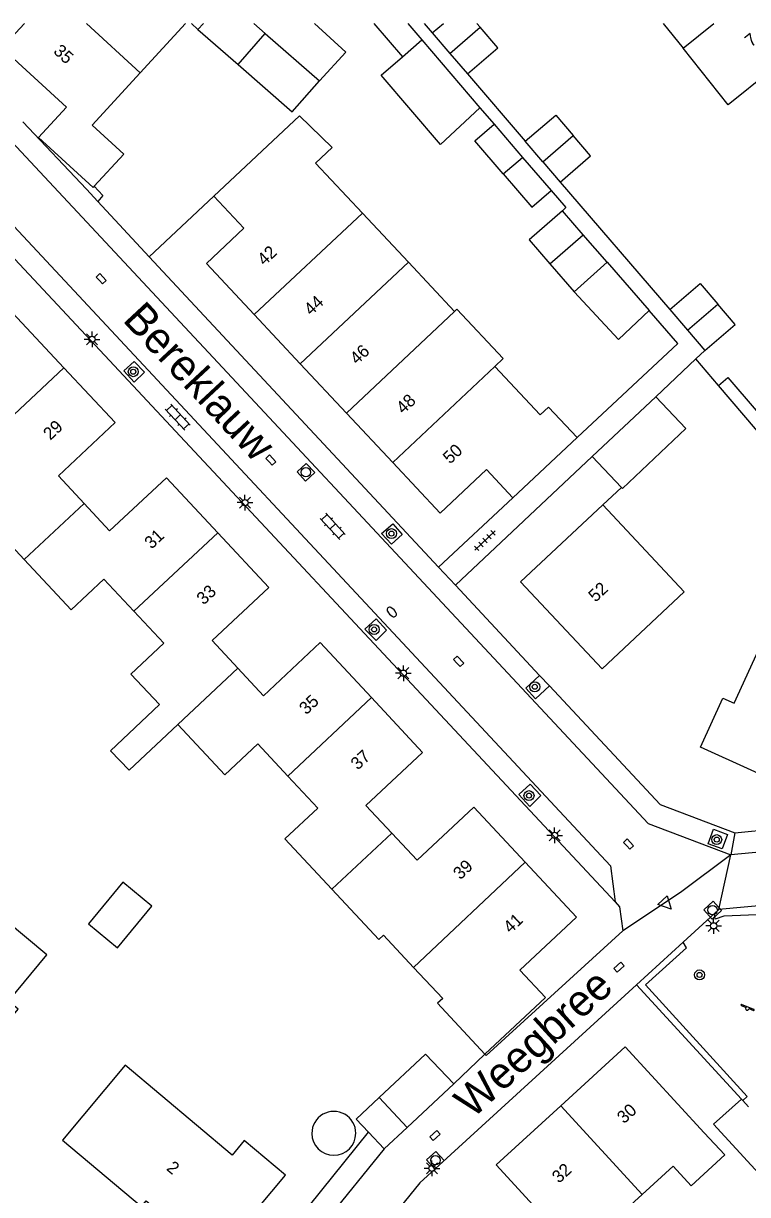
# Model space of a CAD drawing. Extents: x 136000 to 141000, y 400494 to 402006.
# Drawn here: x 137335.3 to 137393.1, y 401906.5 to 402000 of the extents above; entities that cross this region are included whole.
import ezdxf

# ---------------------------------------------------------------- set-up
doc = ezdxf.new("R2010")
doc.units = 0
for name, color, linetype in [('gg-afsc-erfafscheiding', 7, 'Continuous'), ('gg-afsc-muur', 7, 'Continuous'), ('gg-anno-huisnummerreeks BGT', 7, 'Continuous'), ('gg-anno-openbare ruimte label', 7, 'Continuous'), ('gg-bbg-bijgebouw', 7, 'Continuous'), ('gg-bbg-gedigitaliseerde bebouwing', 7, 'Continuous'), ('gg-bbg-gedigitaliseerde bijgebouw', 7, 'Continuous'), ('gg-bbg-hoofdgebouw', 7, 'Continuous'), ('gg-bbg-luifel en loopbrug', 7, 'Continuous'), ('gg-bbg-tussenscheiding', 7, 'Continuous'), ('gg-knt-verharding', 7, 'Continuous'), ('gg-knt-verharding nz', 7, 'Continuous'), ('gt-grn-groengrens', 7, 'Continuous'), ('gt-grn-weggrens', 7, 'Continuous'), ('gt-symb-boom', 7, 'Continuous'), ('gt-symb-brandkraan', 7, 'Continuous'), ('gt-symb-klinker verharding', 7, 'Continuous'), ('gt-symb-kolk', 7, 'Continuous'), ('gt-symb-lichtmast', 7, 'Continuous'), ('gt-symb-rioolschacht', 7, 'Continuous'), ('gt-symb-speelvoorziening', 7, 'Continuous'), ('gt-symb-tegel verharding', 7, 'Continuous'), ('gt-symb-waterafsluiter', 7, 'Continuous')]:
    doc.layers.add(name, color=color, linetype=linetype)

# ---------------------------------------------------------------- blocks, each defined once
blk = doc.blocks.new('gt0-SV')
at = {"layer": 'gt-symb-speelvoorziening'}
for p, q in [((-0.477, 0.255), (-0.08, 0.096)), ((0.542, -0.076), (-0.449, 0.324)), ((0.125, 0.014), (0.515, -0.143))]:
    blk.add_line(p, q, dxfattribs=at)
for centre, radius, start, end in [((-0.466, 0.291), 0.0369, 63.6251, 252.66016), ((-0.002, -0.005), 0.128, 127.68665, 8.59861), ((0.531, -0.111), 0.0363, 243.50852, 72.54358)]:
    blk.add_arc(centre, radius, start, end, dxfattribs=at)
blk = doc.blocks.new('gt0-WAFSL')
at = {"layer": 'gt-symb-waterafsluiter'}
for p, q in [((-0.5, -0.333), (0, 0.667)), ((0, 0.667), (0.5, -0.333)), ((0.5, -0.333), (-0.5, -0.333))]:
    blk.add_line(p, q, dxfattribs=at)
blk = doc.blocks.new('gt0-BOOM')
at = {"layer": 'gt-symb-boom'}
for radius in [0.4, 0.2]:
    blk.add_circle((0, 0), radius, dxfattribs=at)
blk = doc.blocks.new('gt0-RS')
at = {"layer": 'gt-symb-rioolschacht'}
blk.add_lwpolyline([(-0.5, -0.5), (0.5, -0.5), (0.5, 0.5), (-0.5, 0.5)], close=True, dxfattribs=at)
blk.add_circle((0, 0), 0.375, dxfattribs=at)
blk = doc.blocks.new('gt0-LMAST')
at = {"layer": 'gt-symb-lichtmast'}
for p, q in [((-0.182, 0.173), (-0.447, 0.438)), ((-0.005, 0.246), (-0.005, 0.621)), ((0.172, 0.173), (0.437, 0.438)), ((-0.255, -0.004), (-0.63, -0.004)), ((-0.182, -0.181), (-0.447, -0.446)), ((-0.005, -0.254), (-0.005, -0.629)), ((0.437, -0.446), (0.172, -0.181)), ((0.245, -0.004), (0.62, -0.004))]:
    blk.add_line(p, q, dxfattribs=at)
blk.add_circle((-0.005, -0.004), 0.25, dxfattribs=at)
blk = doc.blocks.new('gt0-KOLK')
at = {"layer": 'gt-symb-kolk'}
blk.add_lwpolyline([(0, 0), (0.375, 0), (0.375, 0.4), (-0.375, 0.4), (-0.375, 0), (0, 0)], dxfattribs=at)
blk = doc.blocks.new('gt0-BR')
at = {"layer": 'gt-symb-brandkraan'}
for centre, radius, start, end in [((-0.244, 0), 0.206, 107.56694, 252.43307), ((0.599, -2.664), 3, 106.89205, 107.56694), ((0, -0.691), 0.938, 73.10799, 106.89205), ((-0.599, -2.664), 3, 72.43309, 73.10799), ((0.244, 0), 0.206, 287.56695, 72.43309), ((0.599, 2.664), 3, 252.43307, 253.10797), ((0, 0.691), 0.938, 253.10797, 286.89206), ((-0.599, 2.664), 3, 286.89206, 287.56695)]:
    blk.add_arc(centre, radius, start, end, dxfattribs=at)
blk = doc.blocks.new('gt0-TEG1')
at = {"layer": 'gt-symb-tegel verharding'}
for p, q in [((-1.125, 0), (1.125, 0)), ((-0.9, -0.25), (-0.9, 0.25)), ((-0.45, -0.25), (-0.45, 0.25)), ((0, -0.25), (0, 0.25)), ((0.45, -0.25), (0.45, 0.25)), ((0.9, -0.25), (0.9, 0.25))]:
    blk.add_line(p, q, dxfattribs=at)
blk = doc.blocks.new('gt0-KL1')
at = {"layer": 'gt-symb-klinker verharding'}
for p, q in [((-1.15, 0.3), (1.15, 0.3)), ((-1, -0.3), (-1, 0.3)), ((-0.5, 0.3), (-0.5, 0.45)), ((0, -0.3), (0, 0.3)), ((0.5, 0.3), (0.5, 0.45)), ((1, -0.3), (1, 0.3)), ((-1.15, -0.3), (1.15, -0.3)), ((-0.5, -0.45), (-0.5, -0.3)), ((0.5, -0.45), (0.5, -0.3))]:
    blk.add_line(p, q, dxfattribs=at)

msp = doc.modelspace()

# ---------------------------------------------------------------- linework, layer by layer
at = {"layer": 'gg-afsc-erfafscheiding'}
for p, q in [((137367.313, 402000), (137367.96, 401999.24)), ((137370.76, 401995.98), (137375.39, 401990.59)), ((137371.768, 401993.268), (137372.9, 401991.95)), ((137378.18, 401987.33), (137386.938, 401977.157)), ((137387.571, 401974.458), (137385.29, 401977.079)), ((137387.571, 401974.458), (137379.526, 401966.944)), ((137389.017, 401973.217), (137389.732, 401973.893)), ((137385.826, 401970.196), (137389.017, 401973.217)), ((137390.824, 401971.097), (137389.017, 401973.217))]:
    msp.add_line(p, q, dxfattribs=at)
for points in [[(137340.95, 401986.998), (137341.653, 401986.269), (137341.254, 401985.787)], [(137377.45, 401986.66), (137378.64, 401985.293), (137378.357, 401985.047)], [(137390.824, 401971.097), (137391.577, 401971.738), (137393.83, 401969.11)], [(137401.97, 401961.65), (137396.88, 401963.99), (137390.824, 401971.097)]]:
    msp.add_lwpolyline(points, dxfattribs=at)
at = {"layer": 'gg-afsc-muur'}
for p, q in [((137345.355, 401981.368), (137350.52, 401986.21)), ((137341.254, 401985.787), (137345.355, 401981.368)), ((137381.581, 401961.565), (137383.065, 401962.953)), ((137369.67, 401915.333), (137372.17, 401917.72))]:
    msp.add_line(p, q, dxfattribs=at)
at = {"layer": 'gg-bbg-bijgebouw'}
for p, q in [((137349.247, 401999.516), (137349.691, 402000)), ((137386.938, 401977.157), (137388.34, 401975.519)), ((137388.34, 401975.519), (137389.732, 401973.893)), ((137385.826, 401970.196), (137380.734, 401965.416)), ((137380.734, 401965.416), (137383.065, 401962.953)), ((137383.065, 401962.953), (137383.142, 401962.872)), ((137390.433, 401912.12), (137392.65, 401914.12)), ((137392.65, 401914.12), (137392.752, 401914.008)), ((137392.752, 401914.008), (137393.218, 401913.498)), ((137361.873, 401912.525), (137362.862, 401911.475)), ((137362.862, 401911.475), (137364.115, 401910.146)), ((137364.115, 401910.146), (137365.942, 401911.852))]:
    msp.add_line(p, q, dxfattribs=at)
at = {"layer": 'gg-bbg-gedigitaliseerde bebouwing'}
for p, q in [((137344.632, 401996.057), (137348.258, 402000)), ((137386.412, 402000), (137387.986, 401998.031)), ((137354.619, 401999.204), (137358.94, 401995.41)), ((137344.632, 401996.057), (137340.789, 401991.878)), ((137350.52, 401986.21), (137357.353, 401992.613)), ((137358.645, 401988.848), (137362.381, 401984.863)), ((137340.95, 401986.998), (137340.869, 401986.911)), ((137362.381, 401984.863), (137366.058, 401980.941)), ((137366.058, 401980.941), (137369.745, 401977.008)), ((137377.243, 401969.372), (137379.526, 401966.944)), ((137364.065, 401927.218), (137366.472, 401924.641))]:
    msp.add_line(p, q, dxfattribs=at)
for points in [[(137358.94, 401995.41), (137361.043, 401997.703), (137358.545, 402000)], [(137398.35, 401998.92), (137391.6, 401993.51), (137387.986, 401998.031)], [(137357.353, 401992.613), (137359.97, 401990.09), (137358.645, 401988.848)], [(137340.789, 401991.878), (137343.313, 401989.558), (137340.95, 401986.998)], [(137369.745, 401977.008), (137369.934, 401977.186), (137373.634, 401973.24), (137372.952, 401972.601)], [(137372.952, 401972.601), (137376.57, 401968.741), (137377.243, 401969.372)], [(137331.85, 401966.23), (137334.24, 401963.67), (137331.61, 401961.21), (137335.358, 401957.198)], [(137381.581, 401961.565), (137388.09, 401954.62), (137381.53, 401948.47)], [(137335.358, 401957.198), (137339.11, 401953.18), (137341.74, 401955.63), (137344.132, 401953.072)], [(137344.132, 401953.072), (137346.52, 401950.52), (137343.89, 401948.06)], [(137391.164, 401946.137), (137392.07, 401945.73), (137395.31, 401952.82), (137402.47, 401949.55)], [(137343.89, 401948.06), (137346.185, 401945.621), (137342.271, 401941.938), (137343.743, 401940.374), (137347.64, 401944.04)], [(137347.64, 401944.04), (137351.39, 401940.02), (137354.02, 401942.48), (137356.42, 401939.91)], [(137356.42, 401939.91), (137358.81, 401937.35), (137356.18, 401934.9), (137359.93, 401930.88)], [(137331.835, 401917.611), (137334.892, 401921.305), (137334.118, 401921.945), (137337.18, 401925.651), (137330.802, 401930.927), (137331.861, 401932.209), (137326.714, 401936.459)], [(137359.93, 401930.88), (137363.68, 401926.86), (137364.065, 401927.218)], [(137366.472, 401924.641), (137368.801, 401922.148), (137368.382, 401921.776), (137372.17, 401917.72)], [(137356.249, 401908.039), (137352.939, 401910.813), (137351.972, 401909.66), (137343.433, 401916.824), (137338.416, 401910.857)], [(137389.68, 401911.44), (137391.316, 401909.667), (137388.64, 401907.21), (137387.2, 401908.78), (137384.728, 401906.513)], [(137384.728, 401906.513), (137382.26, 401904.25), (137383.69, 401902.68), (137381, 401900.22), (137373.07, 401908.87)]]:
    msp.add_lwpolyline(points, dxfattribs=at)
at = {"layer": 'gg-bbg-gedigitaliseerde bijgebouw'}
for p, q in [((137363.297, 402000), (137365.58, 401997.34)), ((137365.996, 402000), (137367.12, 401998.68)), ((137367.96, 401999.24), (137368.852, 402000)), ((137371.53, 402000), (137371.79, 401999.697)), ((137349.247, 401999.516), (137352.444, 401996.718)), ((137352.444, 401996.718), (137354.619, 401999.204)), ((137367.96, 401999.24), (137369.36, 401997.61)), ((137365.58, 401997.34), (137367.12, 401998.68)), ((137369.36, 401997.61), (137370.76, 401995.98)), ((137372.9, 401991.95), (137375.175, 401989.305)), ((137376.785, 401988.96), (137375.39, 401990.59)), ((137375.175, 401989.305), (137377.45, 401986.66)), ((137376.785, 401988.96), (137378.18, 401987.33)), ((137377.338, 401980.813), (137380.022, 401983.133)), ((137381.919, 401980.953), (137380.022, 401983.133)), ((137377.338, 401980.813), (137379.28, 401978.566)), ((137381.919, 401980.953), (137385.29, 401977.079)), ((137363.711, 401914.241), (137361.873, 401912.525)), ((137365.942, 401911.852), (137363.711, 401914.241)), ((137396.53, 401905.46), (137390.433, 401912.12))]:
    msp.add_line(p, q, dxfattribs=at)
for points in [[(137370.76, 401995.98), (137373.19, 401998.06), (137371.79, 401999.697)], [(137375.39, 401990.59), (137377.82, 401992.67), (137379.218, 401991.042)], [(137373.632, 401987.982), (137371.36, 401990.63), (137372.9, 401991.95)], [(137378.18, 401987.33), (137380.61, 401989.42), (137379.218, 401991.042)], [(137373.632, 401987.982), (137375.9, 401985.34), (137377.45, 401986.66)], [(137379.28, 401978.566), (137382.842, 401974.778), (137385.29, 401977.079)], [(137386.938, 401977.157), (137389.35, 401979.23), (137390.755, 401977.594)], [(137389.732, 401973.893), (137392.15, 401975.97), (137390.755, 401977.594)], [(137383.142, 401962.872), (137388.22, 401967.65), (137385.826, 401970.196)]]:
    msp.add_lwpolyline(points, dxfattribs=at)
for start, end in [(0.01636, 180.04903), (180.04905, 0.01634)]:
    msp.add_arc((137360.096, 401911.392), 1.753, start, end, dxfattribs=at)
at = {"layer": 'gg-bbg-hoofdgebouw'}
for p, q in [((137333.58, 401998.04), (137335.378, 402000)), ((137357.417, 401972.833), (137353.728, 401976.773)), ((137361.114, 401968.884), (137357.417, 401972.833)), ((137364.803, 401964.944), (137361.114, 401968.884)), ((137379.526, 401966.944), (137374.393, 401962.136)), ((137381.581, 401961.565), (137375.01, 401955.42)), ((137375.01, 401955.42), (137381.53, 401948.47)), ((137373.07, 401908.87), (137378.235, 401913.598))]:
    msp.add_line(p, q, dxfattribs=at)
for points in [[(137333.58, 401998.04), (137338.747, 401993.319), (137336.521, 401990.883), (137340.869, 401986.911)], [(137353.728, 401976.773), (137349.92, 401980.84), (137352.92, 401983.65), (137350.52, 401986.21)], [(137327.88, 401974.85), (137329.91, 401972.66), (137334.44, 401976.89), (137338.542, 401972.502)], [(137338.542, 401972.502), (137342.63, 401968.13), (137338.1, 401963.89), (137340.159, 401961.675)], [(137374.393, 401962.136), (137372.287, 401964.383), (137368.58, 401960.91), (137364.803, 401964.944)], [(137340.159, 401961.675), (137342.19, 401959.49), (137346.72, 401963.72), (137350.829, 401959.32)], [(137350.829, 401959.32), (137354.9, 401954.96), (137350.37, 401950.73), (137352.434, 401948.515)], [(137352.434, 401948.515), (137354.47, 401946.33), (137359.01, 401950.57), (137363.11, 401946.174)], [(137402.47, 401949.55), (137397.47, 401938.55), (137389.39, 401942.21), (137391.164, 401946.137)], [(137363.11, 401946.174), (137367.19, 401941.8), (137362.66, 401937.57), (137364.726, 401935.357)], [(137364.726, 401935.357), (137366.75, 401933.19), (137371.28, 401937.43), (137375.392, 401933.027)], [(137375.392, 401933.027), (137379.48, 401928.65), (137374.95, 401924.41), (137377.01, 401922.24), (137372.17, 401917.72)], [(137378.235, 401913.598), (137383.36, 401918.29), (137389.68, 401911.44)], [(137338.416, 401910.857), (137344.734, 401905.562), (137345.112, 401906.014), (137350.657, 401901.367), (137356.249, 401908.039)]]:
    msp.add_lwpolyline(points, dxfattribs=at)
at = {"layer": 'gg-bbg-luifel en loopbrug'}
for p, q in [((137348.721, 402000), (137349.247, 401999.516)), ((137367.12, 401998.68), (137371.768, 401993.268)), ((137380.022, 401983.133), (137378.357, 401985.047)), ((137365.942, 401911.852), (137369.67, 401915.333))]:
    msp.add_line(p, q, dxfattribs=at)
for points in [[(137371.768, 401993.268), (137368.62, 401990.335), (137363.867, 401995.869), (137365.58, 401997.34)], [(137352.444, 401996.718), (137356.772, 401992.932), (137358.94, 401995.41)], [(137378.357, 401985.047), (137375.687, 401982.724), (137377.338, 401980.813)], [(137340.5, 401928.123), (137342.811, 401926.21), (137345.553, 401929.522), (137343.242, 401931.436), (137340.5, 401928.123)], [(137369.67, 401915.333), (137367.428, 401917.712), (137363.711, 401914.241)]]:
    msp.add_lwpolyline(points, dxfattribs=at)
at = {"layer": 'gg-bbg-tussenscheiding'}
for p, q in [((137340.337, 402000), (137344.632, 401996.057)), ((137353.716, 402000), (137354.619, 401999.204)), ((137387.986, 401998.031), (137390.453, 402000)), ((137369.36, 401997.61), (137371.79, 401999.697)), ((137376.785, 401988.96), (137379.218, 401991.042)), ((137373.632, 401987.982), (137375.175, 401989.305)), ((137353.728, 401976.773), (137362.381, 401984.863)), ((137357.417, 401972.833), (137366.058, 401980.941)), ((137381.919, 401980.953), (137379.28, 401978.566)), ((137388.34, 401975.519), (137390.755, 401977.594)), ((137361.114, 401968.884), (137369.745, 401977.008)), ((137331.85, 401966.23), (137338.542, 401972.502)), ((137364.803, 401964.944), (137372.952, 401972.601)), ((137335.358, 401957.198), (137340.159, 401961.675)), ((137344.132, 401953.072), (137350.829, 401959.32)), ((137347.64, 401944.04), (137352.434, 401948.515)), ((137356.42, 401939.91), (137363.11, 401946.174)), ((137359.93, 401930.88), (137364.726, 401935.357)), ((137366.472, 401924.641), (137375.392, 401933.027)), ((137378.235, 401913.598), (137384.728, 401906.513))]:
    msp.add_line(p, q, dxfattribs=at)
at = {"layer": 'gg-knt-verharding'}
for p, q in [((137335.25, 401992.14), (137340.346, 401986.765)), ((137340.346, 401986.765), (137341.254, 401985.787)), ((137382.56, 401929.86), (137334.62, 401981.169)), ((137345.355, 401981.368), (137368.47, 401956.585)), ((137380.734, 401965.416), (137369.806, 401955.153)), ((137374.393, 401962.136), (137368.47, 401956.585)), ((137368.47, 401956.585), (137369.806, 401955.153)), ((137369.806, 401955.153), (137376.522, 401947.952)), ((137376.522, 401947.952), (137377.311, 401947.107)), ((137390.514, 401928.953), (137387.998, 401926.653)), ((137390.85, 401929.26), (137390.514, 401928.953)), ((137394.89, 401929.64), (137390.85, 401929.26)), ((137387.998, 401926.653), (137384.281, 401923.258)), ((137384.281, 401923.258), (137392.65, 401914.12)), ((137349.67, 401895.14), (137362.862, 401911.475))]:
    msp.add_line(p, q, dxfattribs=at)
for points in [[(137327.132, 401991.708), (137382.19, 401932.74), (137382.56, 401929.86)], [(137343.327, 401972.267), (137344.144, 401971.37), (137344.974, 401972.155), (137344.142, 401973.006), (137343.327, 401972.267)], [(137365.559, 401959.193), (137364.694, 401958.414), (137363.903, 401959.267), (137364.804, 401960.058), (137365.559, 401959.193)], [(137392.12, 401935.37), (137398.56, 401936.01), (137403.12, 401939.27), (137411.33, 401957.374)], [(137362.578, 401951.638), (137363.473, 401950.723), (137364.309, 401951.552), (137363.469, 401952.461), (137362.578, 401951.638)], [(137377.311, 401947.107), (137376.209, 401946.079), (137375.422, 401946.926), (137376.522, 401947.952)], [(137377.311, 401947.107), (137386.15, 401937.63), (137392.12, 401935.37)], [(137375.748, 401937.481), (137376.634, 401938.349), (137375.775, 401939.269), (137374.871, 401938.438), (137375.748, 401937.481)], [(137391.536, 401935.239), (137391.12, 401934.102), (137390.003, 401934.505), (137390.428, 401935.678), (137391.536, 401935.239)], [(137382.56, 401929.86), (137382.92, 401929.47), (137383.19, 401927.55)], [(137383.19, 401927.55), (137372.272, 401917.61), (137372.17, 401917.72)], [(137384.281, 401923.258), (137366.97, 401907.44), (137353.979, 401891.42)]]:
    msp.add_lwpolyline(points, dxfattribs=at)
at = {"layer": 'gg-knt-verharding nz'}
msp.add_line((137364.115, 401910.146), (137351.03, 401894.024), dxfattribs=at)
for points in [[(137334.014, 401990.934), (137385.21, 401936.12), (137391.81, 401933.63)], [(137419.895, 401976.525), (137420.3, 401972.94), (137404.54, 401938.14), (137399.19, 401934.32), (137391.81, 401933.63)]]:
    msp.add_lwpolyline(points, dxfattribs=at)
at = {"layer": 'gt-grn-groengrens'}
for points in [[(137398.4, 401924.399), (137397.924, 401924.03), (137394.548, 401928.863), (137391.253, 401928.737), (137390.553, 401928.493), (137390.514, 401928.953)], [(137392.752, 401914.008), (137393.119, 401914.335), (137384.993, 401923.243), (137388.261, 401926.194), (137387.998, 401926.653)]]:
    msp.add_lwpolyline(points, dxfattribs=at)
at = {"layer": 'gt-grn-weggrens'}
for p in [(137392.12, 401935.37), (137390.85, 401929.26)]:
    msp.add_line(p, (137391.81, 401933.63), dxfattribs=at)
msp.add_lwpolyline([(137391.81, 401933.63), (137387.787, 401930.616), (137383.19, 401927.55)], dxfattribs=at)

# ---------------------------------------------------------------- block references
at = {"layer": 'gt-symb-boom'}
for p in [(137344.08, 401972.196), (137364.701, 401959.269), (137363.317, 401951.618), (137376.144, 401947.04), (137375.685, 401938.352), (137390.676, 401934.838), (137389.307, 401924.037)]:
    msp.add_blockref('gt0-BOOM', p, dxfattribs=at)
at = {"layer": 'gt-symb-brandkraan', "rotation": 132.73204546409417}
msp.add_blockref('gt0-BR', (137364.722, 401953.014), dxfattribs=at)
at = {"layer": 'gt-symb-klinker verharding', "rotation": 133.01389341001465}
for p in [(137347.631, 401968.568), (137360.011, 401959.843)]:
    msp.add_blockref('gt0-KL1', p, dxfattribs=at)
at = {"layer": 'gt-symb-kolk'}
for p, rotation in [((137341.372, 401979.478), -46.94423037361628), ((137354.922, 401964.999), -46.94423037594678), ((137369.919, 401948.936), -46.94423037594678), ((137383.487, 401934.345), -46.94423037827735), ((137383, 401924.5), 42.36616983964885), ((137368.31, 401911.071), 42.36616983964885)]:
    msp.add_blockref('gt0-KOLK', p, dxfattribs=dict(at, rotation=rotation))
at = {"layer": 'gt-symb-lichtmast'}
for p in [(137340.796, 401974.779), (137353.004, 401961.749), (137365.657, 401948.131), (137377.731, 401935.181), (137390.435, 401927.959), (137367.936, 401908.592)]:
    msp.add_blockref('gt0-LMAST', p, dxfattribs=at)
at = {"layer": 'gt-symb-rioolschacht'}
for p, rotation in [((137357.865, 401964.165), -46.94423037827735), ((137390.353, 401929.208), 42.36616983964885), ((137368.207, 401909.244), 42.36616983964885)]:
    msp.add_blockref('gt0-RS', p, dxfattribs=dict(at, rotation=rotation))
at = {"layer": 'gt-symb-speelvoorziening'}
msp.add_blockref('gt0-SV', (137393.113, 401921.353), dxfattribs=at)
at = {"layer": 'gt-symb-tegel verharding', "rotation": 43.7035699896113}
msp.add_blockref('gt0-TEG1', (137372.166, 401958.717), dxfattribs=at)
at = {"layer": 'gt-symb-waterafsluiter', "rotation": -136.4999713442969}
msp.add_blockref('gt0-WAFSL', (137386.578, 401929.765), dxfattribs=at)

# ---------------------------------------------------------------- texts
at = {"layer": 'gg-anno-huisnummerreeks BGT'}
for s, rotation, p in [('7', 38.6, (137393.42, 401998.061)), ('35', 317.5, (137337.637, 401997.695)), ('42', 43.1, (137354.553, 401980.608)), ('44', 43.1, (137358.28, 401976.627)), ('46', 43.1, (137361.948, 401972.709)), ('48', 43.1, (137365.642, 401968.764)), ('29', 43.1, (137337.452, 401966.675)), ('50', 43.1, (137369.375, 401964.777)), ('31', 43.1, (137345.54, 401957.985)), ('33', 43, (137349.701, 401953.528)), ('52', 43.2, (137380.998, 401953.748)), ('35', 43, (137357.895, 401944.761)), ('37', 43, (137362.013, 401940.347)), ('39', 43.1, (137370.199, 401931.589)), ('41', 43.1, (137374.201, 401927.304)), ('30', 42.4, (137383.274, 401912.112)), ('2', 320.1, (137346.661, 401908.513)), ('32', 42.4, (137378.078, 401907.356))]:
    msp.add_text(s, height=1, rotation=rotation, dxfattribs=at).set_placement(p)
at = {"layer": 'gg-anno-openbare ruimte label'}
for s, rotation, p in [('Bereklauw', 313, (137343.155, 401976.288)), ('Weegbree', 42.4, (137371.168, 401912.5))]:
    msp.add_text(s, height=2.5, rotation=rotation, dxfattribs=at).set_placement(p)

doc.saveas('drawing.dxf')
